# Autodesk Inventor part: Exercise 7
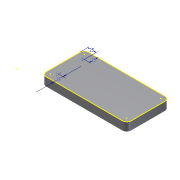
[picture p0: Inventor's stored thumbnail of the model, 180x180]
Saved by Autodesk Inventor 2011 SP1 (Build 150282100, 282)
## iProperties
Created: 2011-02
Part Number: Exercise 7
Document SubType Name: Modeling
Designer: SERGIO
Density: 1 g/cm^3
Author: SERGIO
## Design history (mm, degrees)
sketch "Sketch1"
  geometry: L1 (50.81, 148.628)-(300.81, 148.628); L2 (300.81, 148.628)-(300.81, 23.628); L3 (300.81, 23.628)-(50.81, 23.628); L4 (50.81, 23.628)-(50.81, 148.628); 3 further points
  constraints: 8 end point, 2 midpoint, 2 parallel, 1 horizontal, 1 perpendicular
  dimensions: "d0" = 250 distance of L2.end L3.end; "d1" = 125 distance of L1.end L2.end
extrude "Extrusion1" new body sketch "Sketch1" distance "d2" = 25; taper "d3" = 0 deg
fillet "Fillet1" dims "d4" = 12.5
sketch "Sketch2"
  geometry: L1 (63.31, 148.628)-(288.31, 148.628) reference; L2 (50.81, 36.128)-(50.81, 136.128) reference; L3 (288.31, 23.628)-(63.31, 23.628) reference; L4 (300.81, 136.128)-(300.81, 36.128) reference; A1 r 12.5 centre (63.31, 136.128) between (63.31, 148.628) and (50.81, 136.128) reference; A2 r 12.5 centre (63.31, 36.128) between (50.81, 36.128) and (63.31, 23.628) reference; A3 r 12.5 centre (288.31, 36.128) between (288.31, 23.628) and (300.81, 36.128) reference; A4 r 12.5 centre (288.31, 136.128) between (300.81, 136.128) and (288.31, 148.628) reference; 3 further points
  constraints: 1 vertical alignment
  dimensions: "d17" = 25 distance from line of L3 point (75.81, 48.628); "d18" = 25 distance from line of L1 point (75.81, 123.628); "d19" = 25 distance from line of point (75.81, 123.628) L2
body "Solid1"
